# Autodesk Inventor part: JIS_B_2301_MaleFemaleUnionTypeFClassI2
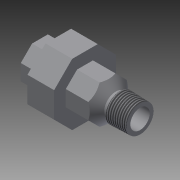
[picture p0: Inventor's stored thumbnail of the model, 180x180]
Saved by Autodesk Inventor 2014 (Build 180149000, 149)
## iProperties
Shininess: 64.0
Length Units: 11269
Angle Units: 11279
Time Units: 11290
Mass Units: 11283
Length Display Precision: 3
Angle Display Precision: 2
Created: 2002-11
Part Number: JIS_B_2301_MaleFemaleUnionTypeFClassI2
Document SubType Name: Modeling
Designer: batisova
Material: Cast Iron
Density: 1 g/cm^3
Appearance: Default
Density: 0.0
Volumn: 0.0
Area: 0.0
PropertySet Name: Model Information
Control State: 0
Master: False
Checked Out: False
Author: batisova
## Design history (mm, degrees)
sketch "Sketch1"
  geometry: L1 (0, 0)-(60, 0); L2 (0, 0)-(0, 7.475); L3 (0, 7.475)-(0, 12.448); L4 (0, 12.448)-(11, 12.448); L5 (40.5, 8.331)-(9, 8.331); L6 (9, 8.331)-(9, 7.194); L7 (9, 7.194)-(0, 7.475); L8 (11, 12.448)-(11, 20.024); L9 (11, 20.024)-(27, 20.024); L10 (27, 20.024)-(27, 12.448); L11 (27, 12.448)-(40.5, 12.448); L12 (40.5, 12.448)-(45.5, 7); L13 (45.5, 7)-(48, 7); L14 (48, 7)-(48, 8.508); L15 (48, 8.508)-(60, 8.133); L16 (60, 8.133)-(60, 5.831); L17 (60, 5.831)-(45.5, 5.831); L18 (45.5, 5.831)-(40.5, 8.331); L19 (60, 5.831)-(60, 0); L20 (53.65, 8.331)-(53.65, 0); L21 (40.5, 12.448)-(40.5, 8.331); L22 (45.5, 5.831)-(45.5, 7); L23 (0, 0)-(-74, 0); L24 (-74, 0)-(-74, 20.024); L25 (-74, 0)-(-66.337, 18.5); L26 (-74, 0)-(-81.663, 18.5); L27 (-78.763, 11.5)-(-69.237, 11.5); L28 (-81.663, 18.5)-(-66.337, 18.5); L29 (-74, 20.024)-(11, 20.024); L30 (0, 12.448)-(-74, 12.448); A1 r 12.448 centre (-74, 0) between (-78.763, 11.5) and (-74, 12.448); A2 r 20.024 centre (-74, 0) between (-74, 20.024) and (-81.663, 18.5)
  constraints: 60 end point, 10 parallel, 6 perpendicular, 5 point on circle, 5 point on line, 4 coincident, 3 horizontal, 2 centre point, 2 collinear, 2 vertical, 1 concentric, 1 other
  dimensions: "d0" = 9 horizontal distance of L6.end L2.end (= l1); "d1" = 1.78991 deg angle of L1 L7; "d2" = 16.662 diameter of L5 L1 (= D); "d7" = 14.95 diameter of L2.end L1 (derived); "d8" = 16 distance of L8.end L9.end (derived); "d9" = 6.35 distance between parallel lines of L16 L20 (derived); "d10" = 16.662 diameter of L20.start L1 (derived); "d11" = 2.5 distance from line of L17 L20.start (derived); "d12" = 12 horizontal distance of L14.end L15.end (derived); "d13" = 5 horizontal distance of L11.end L12.end (derived); "d14" = 60 distance of L1.start L1.end (derived); "d15" = 11 distance between parallel lines of L3 L8 (derived); "d16" = 14 diameter of L13 L1 (derived); "d17" = 2.5 distance of L12.end L13.end (derived); "d19" = 11.5 distance between parallel lines of L23 L27 (derived); "d21" = 74 distance of L2.start L23.end (derived); "d22" = 18.5 distance between parallel lines of L23 L28 (derived); "d23" = 45 deg angle of L25 L26 (derived)
revolve "Revolution1" sketch "Sketch1" stored, may be unused: angle "d18" = 90 deg
sketch "Sketch2"
  geometry: L1 (0, 0)-(0, -12.448); L2 (0, 0)-(4.763, -11.5); L3 (0, 0)-(-4.763, -11.5); L4 (-4.763, -11.5)-(4.763, -11.5); C1 r 12.448 at (0, 0) reference; A1 r 12.448 centre (0, 0) between (4.763, -11.5) and (-4.763, -11.5)
  constraints: 8 end point, 3 point on circle, 2 concentric, 1 centre point, 1 perpendicular, 1 symmetric about line, 1 vertical, 1 other
  dimensions: "d24" = 11.5 distance from line of L4 L1.start (derived)
extrude "Extrude1" cut sketch "Sketch2" taper "d3" = 0 deg; stored distance "d20" = 10
sketch "Sketch3"
  geometry: L1 (0, 0)-(0, -12.448); L2 (0, 0)-(-4.763, -11.5); L3 (0, 0)-(4.763, -11.5); L4 (-4.763, -11.5)-(4.763, -11.5); L5 (4.763, -11.5)-(-4.763, -11.5) reference; C1 r 12.448 at (0, 0) reference; A1 r 12.448 centre (0, 0) between (-4.763, -11.5) and (4.763, -11.5)
  constraints: 8 end point, 3 point on circle, 2 concentric, 1 centre point, 1 collinear, 1 perpendicular, 1 symmetric about line, 1 vertical, 1 other
  dimensions: "d25" = 11.5 distance from line of L1.start L4 (derived)
extrude "Extrude2" cut sketch "Sketch3" taper "d4" = 0 deg; stored distance "d39" = 10
workplane "Work Plane1"
sketch "Sketch4"
  geometry: L1 (0, 0)-(0, -20.024); L2 (0, 0)-(7.663, -18.5); L3 (0, 0)-(-7.663, -18.5); L4 (-7.663, -18.5)-(7.663, -18.5); L5 (-4.763, -11.5)-(4.763, -11.5) reference; L6 (-4.763, -11.5)-(4.763, -11.5) reference; C1 r 20.024 at (0, 0) reference; A1 r 20.024 centre (0, 0) between (-7.663, -18.5) and (7.663, -18.5)
  constraints: 8 end point, 3 point on circle, 2 concentric, 1 centre point, 1 parallel, 1 perpendicular, 1 symmetric about line, 1 vertical, 1 other
  dimensions: "d26" = 18.5 distance from line of L1.start L4 (derived)
extrude "Extrude3" cut sketch "Sketch4" taper "d5" = 0 deg; stored distance "d47" = 10
thread "Thread1" dims "d60" = 10, "d61" = 0
body "Solid1"
pattern_circular "Circular Pattern1" dims "d28" = 360 deg
thread "Thread2" dims "d104" = 10, "d105" = 0
other parameters: "b1" = 19 [user parameter; used in 1 equation term], "b2" = 41 [user parameter], "B" = 37 [user parameter], "B1" = 23 [user parameter], "ll" = 8 [user parameter; used in 1 equation term], "H" = 16 [user parameter; used in 1 equation term], "D" = 16.662 [user parameter; used in 1 equation term], "l1" = 9 [user parameter; used in 1 equation term], "MD" = 14.95 [user parameter], "d6" = -27 (= ll - b1 - H), "a" = 6.35 [user parameter], "A2" = 14 [user parameter], "tt" = 2.5 [user parameter], "l2" = 12 [user parameter]
